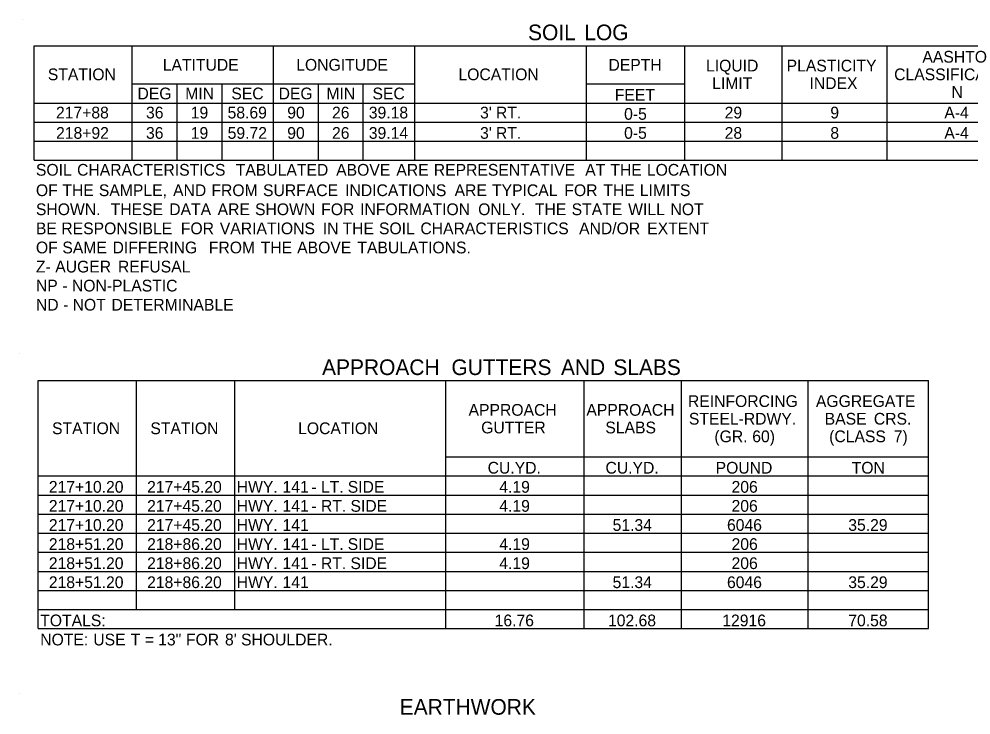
# Model space of a CAD drawing. Extents: x 1334738 to 1334853, y 402732 to 402753.
# Drawn here: x 1334779.92 to 1334792.08, y 402743.25 to 402752.13 of the extents above; entities that cross this region are included whole.
import ezdxf

# ---------------------------------------------------------------- set-up
doc = ezdxf.new("R2010")
doc.units = 0
doc.layers.add('Default', color=7, linetype='Continuous')

msp = doc.modelspace()

# ---------------------------------------------------------------- linework, layer by layer
at = {"layer": 'Default'}
for p, q in [((1334779.961, 402752.134), (1334779.961, 402752.134)), ((1334780.108, 402751.792), (1334794.038, 402751.792)), ((1334780.108, 402750.33), (1334780.108, 402751.792)), ((1334780.108, 402750.33), (1334780.108, 402751.792)), ((1334781.363, 402750.33), (1334781.363, 402751.792)), ((1334783.167, 402750.33), (1334783.167, 402751.792)), ((1334784.971, 402750.33), (1334784.971, 402751.792)), ((1334787.164, 402750.33), (1334787.164, 402751.792)), ((1334788.42, 402750.33), (1334788.42, 402751.792)), ((1334789.663, 402750.33), (1334789.663, 402751.792)), ((1334791.003, 402750.33), (1334791.003, 402751.792)), ((1334781.363, 402751.305), (1334784.971, 402751.305)), ((1334781.936, 402750.33), (1334781.936, 402751.305)), ((1334781.936, 402750.33), (1334781.936, 402751.305)), ((1334782.509, 402750.33), (1334782.509, 402751.305)), ((1334782.509, 402750.33), (1334782.509, 402751.305)), ((1334783.167, 402750.33), (1334783.167, 402751.305)), ((1334783.74, 402750.33), (1334783.74, 402751.305)), ((1334783.74, 402750.33), (1334783.74, 402751.305)), ((1334784.312, 402750.33), (1334784.312, 402751.305)), ((1334784.312, 402750.33), (1334784.312, 402751.305)), ((1334784.971, 402750.33), (1334784.971, 402751.305)), ((1334787.164, 402751.305), (1334788.42, 402751.305)), ((1334780.108, 402751.061), (1334794.038, 402751.061)), ((1334781.363, 402750.33), (1334781.363, 402751.061)), ((1334784.971, 402751.061), (1334788.42, 402751.061)), ((1334787.164, 402750.33), (1334787.164, 402751.061)), ((1334788.42, 402751.061), (1334794.038, 402751.061)), ((1334788.42, 402750.33), (1334788.42, 402751.061)), ((1334789.663, 402750.33), (1334789.663, 402751.061)), ((1334791.003, 402750.33), (1334791.003, 402751.061)), ((1334780.108, 402750.817), (1334794.038, 402750.817)), ((1334780.108, 402750.574), (1334794.038, 402750.574)), ((1334780.108, 402750.33), (1334794.038, 402750.33)), ((1334779.918, 402747.858), (1334779.918, 402747.858)), ((1334780.162, 402747.517), (1334791.533, 402747.517)), ((1334780.162, 402744.348), (1334780.162, 402747.517)), ((1334780.162, 402744.348), (1334780.162, 402747.517)), ((1334781.417, 402744.592), (1334781.417, 402747.517)), ((1334782.673, 402744.592), (1334782.673, 402747.517)), ((1334785.366, 402744.348), (1334785.366, 402747.517)), ((1334787.133, 402744.348), (1334787.133, 402747.517)), ((1334788.377, 402744.348), (1334788.377, 402747.517)), ((1334789.997, 402744.348), (1334789.997, 402747.517)), ((1334791.533, 402744.348), (1334791.533, 402747.517)), ((1334785.366, 402746.542), (1334791.533, 402746.542)), ((1334787.133, 402744.348), (1334787.133, 402746.542)), ((1334788.377, 402744.348), (1334788.377, 402746.542)), ((1334789.997, 402744.348), (1334789.997, 402746.542)), ((1334791.533, 402744.348), (1334791.533, 402746.542)), ((1334780.162, 402746.298), (1334791.533, 402746.298)), ((1334781.417, 402744.592), (1334781.417, 402746.298)), ((1334782.673, 402744.592), (1334782.673, 402746.298)), ((1334785.366, 402744.348), (1334785.366, 402746.298)), ((1334780.162, 402746.054), (1334791.533, 402746.054)), ((1334780.162, 402745.811), (1334791.533, 402745.811)), ((1334780.162, 402745.567), (1334791.533, 402745.567)), ((1334780.162, 402745.323), (1334791.533, 402745.323)), ((1334780.162, 402745.079), (1334791.533, 402745.079)), ((1334780.162, 402744.836), (1334791.533, 402744.836)), ((1334780.162, 402744.592), (1334791.533, 402744.592)), ((1334780.162, 402744.348), (1334791.533, 402744.348)), ((1334779.916, 402743.525), (1334779.916, 402743.525))]:
    msp.add_line(p, q, dxfattribs=at)

# ---------------------------------------------------------------- texts
for s, height, p in [('SOIL', 0.2, (1334786.418, 402751.863)), (' LOG', 0.2, (1334787.062, 402751.863)), ('AASHTO', 0.15, (1334791.455, 402751.577)), ('LATITUDE', 0.15, (1334781.752, 402751.474)), ('LONGITUDE', 0.15, (1334783.457, 402751.474)), ('DEPTH', 0.15, (1334787.445, 402751.474)), ('LIQUID', 0.15, (1334788.691, 402751.464)), ('PLASTICITY', 0.15, (1334789.721, 402751.464)), ('STATION', 0.15, (1334780.284, 402751.352)), ('LOCATION', 0.15, (1334785.529, 402751.352)), ('CLASSIFICATIO', 0.15, (1334791.094, 402751.352)), ('LIMIT', 0.15, (1334788.77, 402751.239)), ('INDEX', 0.15, (1334790.013, 402751.239)), ('N', 0.15, (1334791.826, 402751.127)), ('DEG', 0.15, (1334781.429, 402751.108)), ('MIN', 0.15, (1334782.039, 402751.108)), ('SEC', 0.15, (1334782.628, 402751.108)), ('DEG', 0.15, (1334783.232, 402751.108)), ('MIN', 0.15, (1334783.842, 402751.108)), ('SEC', 0.15, (1334784.431, 402751.108)), ('FEET', 0.15, (1334787.526, 402751.091)), ('217+88', 0.15, (1334780.388, 402750.864)), ('36', 0.15, (1334781.538, 402750.864)), ('19', 0.15, (1334782.11, 402750.864)), ('58.69', 0.15, (1334782.58, 402750.864)), ('90', 0.15, (1334783.342, 402750.864)), ('26', 0.15, (1334783.914, 402750.864)), ('39.18', 0.15, (1334784.384, 402750.864)), ("3'", 0.15, (1334785.805, 402750.864)), (' RT.', 0.15, (1334785.952, 402750.864)), ('0-5', 0.15, (1334787.645, 402750.847)), ('29', 0.15, (1334788.929, 402750.864)), ('9', 0.15, (1334790.279, 402750.864)), ('A-4', 0.15, (1334791.735, 402750.864)), ('218+92', 0.15, (1334780.389, 402750.604)), ('36', 0.15, (1334781.538, 402750.604)), ('19', 0.15, (1334782.11, 402750.604)), ('59.72', 0.15, (1334782.581, 402750.604)), ('90', 0.15, (1334783.342, 402750.604)), ('26', 0.15, (1334783.914, 402750.604)), ('39.14', 0.15, (1334784.384, 402750.604)), ("3'", 0.15, (1334785.805, 402750.604)), (' RT.', 0.15, (1334785.952, 402750.604)), ('0-5', 0.15, (1334787.645, 402750.604)), ('28', 0.15, (1334788.929, 402750.604)), ('8', 0.15, (1334790.279, 402750.604)), ('A-4', 0.15, (1334791.735, 402750.604)), ('SOIL', 0.15, (1334780.132, 402750.133)), (' CHARACTERISTICS', 0.15, (1334780.602, 402750.133)), (' TABULATED', 0.15, (1334782.629, 402750.133)), (' ABOVE', 0.15, (1334783.911, 402750.133)), (' ARE', 0.15, (1334784.68, 402750.133)), (' REPRESENTATIVE', 0.15, (1334785.158, 402750.133)), (' AT', 0.15, (1334787.092, 402750.133)), (' THE', 0.15, (1334787.414, 402750.133)), (' LOCATION', 0.15, (1334787.88, 402750.133)), ('OF', 0.15, (1334780.132, 402749.872)), (' THE', 0.15, (1334780.414, 402749.872)), (' SAMPLE,', 0.15, (1334780.88, 402749.872)), (' AND', 0.15, (1334781.828, 402749.872)), (' FROM', 0.15, (1334782.318, 402749.872)), (' SURFACE', 0.15, (1334782.977, 402749.872)), (' INDICATIONS', 0.15, (1334784.026, 402749.872)), (' ARE', 0.15, (1334785.424, 402749.872)), (' TYPICAL', 0.15, (1334785.902, 402749.872)), (' FOR', 0.15, (1334786.826, 402749.872)), (' THE', 0.15, (1334787.324, 402749.872)), (' LIMITS', 0.15, (1334787.79, 402749.872)), ('SHOWN.', 0.15, (1334780.132, 402749.629)), ('  THESE', 0.15, (1334780.975, 402749.629)), (' DATA', 0.15, (1334781.779, 402749.629)), (' ARE', 0.15, (1334782.397, 402749.629)), (' SHOWN', 0.15, (1334782.875, 402749.629)), (' FOR', 0.15, (1334783.72, 402749.629)), (' INFORMATION', 0.15, (1334784.217, 402749.629)), (' ONLY.', 0.15, (1334785.725, 402749.629)), ('  THE', 0.15, (1334786.394, 402749.629)), (' STATE', 0.15, (1334786.919, 402749.629)), (' WILL', 0.15, (1334787.641, 402749.629)), (' NOT', 0.15, (1334788.181, 402749.629)), ('BE', 0.15, (1334780.132, 402749.385)), (' RESPONSIBLE', 0.15, (1334780.401, 402749.385)), (' FOR', 0.15, (1334781.927, 402749.385)), (' VARIATIONS', 0.15, (1334782.425, 402749.385)), (' IN', 0.15, (1334783.741, 402749.385)), (' THE', 0.15, (1334783.992, 402749.385)), (' SOIL', 0.15, (1334784.458, 402749.385)), (' CHARACTERISTICS', 0.15, (1334784.987, 402749.385)), (' AND/OR', 0.15, (1334787.014, 402749.385)), (' EXTENT', 0.15, (1334787.884, 402749.385)), ('OF', 0.15, (1334780.132, 402749.141)), (' SAME', 0.15, (1334780.414, 402749.141)), (' DIFFERING', 0.15, (1334781.055, 402749.141)), ('  FROM', 0.15, (1334782.229, 402749.141)), (' THE', 0.15, (1334782.947, 402749.141)), (' ABOVE', 0.15, (1334783.413, 402749.141)), (' TABULATIONS.', 0.15, (1334784.182, 402749.141)), ('Z-', 0.15, (1334780.132, 402748.897)), (' AUGER', 0.15, (1334780.323, 402748.897)), (' REFUSAL', 0.15, (1334781.124, 402748.897)), ('NP', 0.15, (1334780.132, 402748.654)), (' NON-PLASTIC', 0.15, (1334780.536, 402748.654)), (' -', 0.15, (1334780.414, 402748.654)), ('ND', 0.15, (1334780.132, 402748.41)), (' NOT', 0.15, (1334780.545, 402748.41)), (' DETERMINABLE', 0.15, (1334781.041, 402748.41)), (' -', 0.15, (1334780.424, 402748.41)), ('APPROACH', 0.2, (1334783.787, 402747.587)), (' GUTTERS', 0.2, (1334785.365, 402747.587)), (' AND', 0.2, (1334786.764, 402747.587)), (' SLABS', 0.2, (1334787.433, 402747.587)), ('REINFORCING', 0.15, (1334788.46, 402747.179)), ('AGGREGATE', 0.15, (1334790.095, 402747.179)), ('APPROACH', 0.15, (1334785.658, 402747.067)), ('APPROACH', 0.15, (1334787.163, 402747.067)), ('STEEL-RDWY.', 0.15, (1334788.472, 402746.954)), ('BASE', 0.15, (1334790.207, 402746.954)), (' CRS.', 0.15, (1334790.779, 402746.954)), ('STATION', 0.15, (1334780.338, 402746.832)), ('STATION', 0.15, (1334781.594, 402746.832)), ('LOCATION', 0.15, (1334783.481, 402746.832)), ('GUTTER', 0.15, (1334785.819, 402746.842)), ('SLABS', 0.15, (1334787.405, 402746.842)), ('(GR.', 0.15, (1334788.798, 402746.729)), (' 60)', 0.15, (1334789.226, 402746.729)), ('(CLASS', 0.15, (1334790.264, 402746.729)), (' 7)', 0.15, (1334791.033, 402746.729)), ('CU.YD.', 0.15, (1334785.902, 402746.328)), ('CU.YD.', 0.15, (1334787.407, 402746.328)), ('POUND', 0.15, (1334788.814, 402746.328)), ('TON', 0.15, (1334790.552, 402746.328)), ('217+10.20', 0.15, (1334780.297, 402746.084)), ('217+45.20', 0.15, (1334781.552, 402746.084)), ('HWY.', 0.15, (1334782.697, 402746.084)), (' 141', 0.15, (1334783.226, 402746.084)), (' LT.', 0.15, (1334783.717, 402746.084)), (' SIDE', 0.15, (1334784.059, 402746.084)), ('4.19', 0.15, (1334786.051, 402746.084)), ('206', 0.15, (1334789.017, 402746.084)), (' -', 0.15, (1334783.595, 402746.084)), ('217+10.20', 0.15, (1334780.297, 402745.841)), ('217+45.20', 0.15, (1334781.552, 402745.841)), ('HWY.', 0.15, (1334782.697, 402745.841)), (' 141', 0.15, (1334783.226, 402745.841)), (' RT.', 0.15, (1334783.717, 402745.841)), (' SIDE', 0.15, (1334784.094, 402745.841)), ('4.19', 0.15, (1334786.051, 402745.841)), ('206', 0.15, (1334789.017, 402745.841)), (' -', 0.15, (1334783.595, 402745.841)), ('217+10.20', 0.15, (1334780.297, 402745.597)), ('217+45.20', 0.15, (1334781.552, 402745.597)), ('HWY.', 0.15, (1334782.697, 402745.597)), (' 141', 0.15, (1334783.226, 402745.597)), ('51.34', 0.15, (1334787.498, 402745.597)), ('6046', 0.15, (1334788.959, 402745.597)), ('35.29', 0.15, (1334790.508, 402745.597)), ('218+51.20', 0.15, (1334780.297, 402745.353)), ('218+86.20', 0.15, (1334781.552, 402745.353)), ('HWY.', 0.15, (1334782.697, 402745.353)), (' 141', 0.15, (1334783.226, 402745.353)), (' LT.', 0.15, (1334783.717, 402745.353)), (' SIDE', 0.15, (1334784.059, 402745.353)), ('4.19', 0.15, (1334786.051, 402745.353)), ('206', 0.15, (1334789.017, 402745.353)), (' -', 0.15, (1334783.595, 402745.353)), ('218+51.20', 0.15, (1334780.297, 402745.109)), ('218+86.20', 0.15, (1334781.552, 402745.109)), ('HWY.', 0.15, (1334782.697, 402745.109)), (' 141', 0.15, (1334783.226, 402745.109)), (' RT.', 0.15, (1334783.717, 402745.109)), (' SIDE', 0.15, (1334784.094, 402745.109)), ('4.19', 0.15, (1334786.051, 402745.109)), ('206', 0.15, (1334789.017, 402745.109)), (' -', 0.15, (1334783.595, 402745.109)), ('218+51.20', 0.15, (1334780.297, 402744.866)), ('218+86.20', 0.15, (1334781.552, 402744.866)), ('HWY.', 0.15, (1334782.697, 402744.866)), (' 141', 0.15, (1334783.226, 402744.866)), ('51.34', 0.15, (1334787.498, 402744.866)), ('6046', 0.15, (1334788.959, 402744.866)), ('35.29', 0.15, (1334790.508, 402744.866)), ('TOTALS:', 0.15, (1334780.187, 402744.378)), ('16.76', 0.15, (1334785.991, 402744.378)), ('102.68', 0.15, (1334787.439, 402744.378)), ('12916', 0.15, (1334788.899, 402744.378)), ('70.58', 0.15, (1334790.508, 402744.378)), ('NOTE:', 0.15, (1334780.187, 402744.134)), (' USE', 0.15, (1334780.809, 402744.134)), (' T', 0.15, (1334781.287, 402744.134)), (' =', 0.15, (1334781.469, 402744.134)), (' 13"', 0.15, (1334781.638, 402744.134)), (' FOR', 0.15, (1334781.993, 402744.134)), (" 8'", 0.15, (1334782.491, 402744.134)), (' SHOULDER.', 0.15, (1334782.696, 402744.134)), ('EARTHWORK', 0.2, (1334784.779, 402743.249))]:
    msp.add_text(s, height=height, dxfattribs=at).set_placement(p)

doc.saveas('drawing.dxf')
